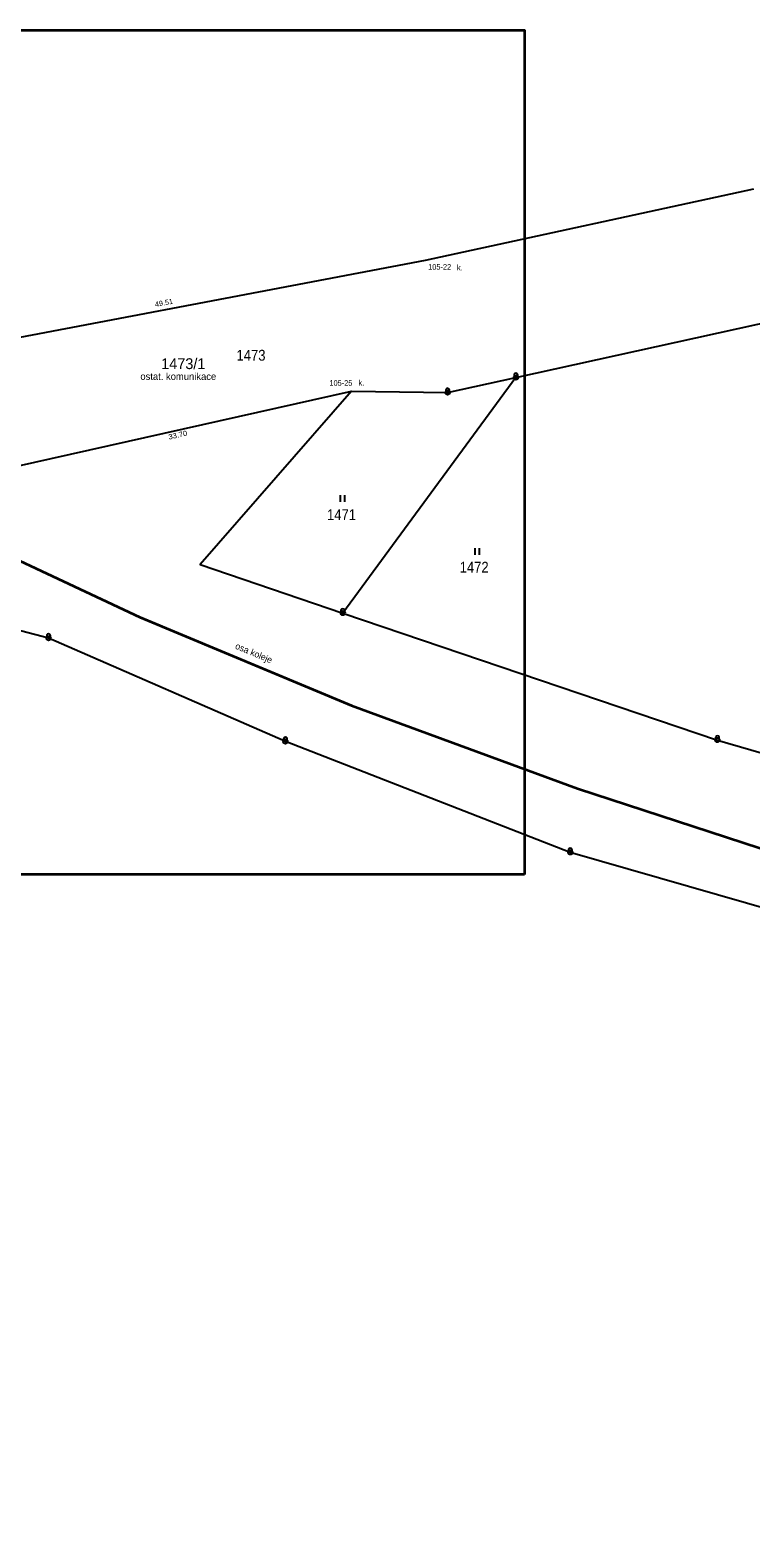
# Model space of a CAD drawing. Extents: x -871901 to -870967, y -1075952 to -1074892.
# Drawn here: x -871353.8 to -871287.2, y -1075423.5 to -1075284.3 of the extents above; entities that cross this region are included whole.
import ezdxf
from ezdxf.enums import TextEntityAlignment as Align

# ---------------------------------------------------------------- set-up
doc = ezdxf.new("R2010")
doc.units = 0
doc.header["$LTSCALE"] = 0.4
for name, color, linetype, lineweight in [('1', 7, 'Continuous', 25), ('10', 7, 'Continuous', 35), ('24', 7, 'Continuous', 25), ('25', 7, 'Continuous', 25), ('55', 7, 'Continuous', 35), ('62', 7, 'Continuous', 25)]:
    doc.layers.add(name, color=color, linetype=linetype, lineweight=lineweight)
for name, color, linetype in [('18', 7, 'Continuous'), ('54', 7, 'Continuous'), ('56', 7, 'Continuous'), ('61', 7, 'Continuous')]:
    doc.layers.add(name, color=color, linetype=linetype)

msp = doc.modelspace()

# ---------------------------------------------------------------- linework, layer by layer
at = {"layer": '1'}
for p, q in [((-871317.28, -1075305.51), (-871286.96, -1075298.91)), ((-871308.94, -1075316.35), (-871324.93, -1075338.1)), ((-871356.98, -1075324.98), (-871324.12, -1075317.6))]:
    msp.add_line(p, q, dxfattribs=at)
for points in [[(-871377.38, -1075316.93), (-871365.94, -1075314.75), (-871317.28, -1075305.51)], [(-871324.12, -1075317.6), (-871315.25, -1075317.74), (-871308.94, -1075316.35), (-871284.79, -1075311.01)], [(-871324.12, -1075317.6), (-871338.12, -1075333.63), (-871324.93, -1075338.1), (-871290.33, -1075349.84), (-871243.8, -1075363.33)], [(-871212.24, -1075392.84), (-871218.94, -1075390.82), (-871230.33, -1075381.38), (-871303.93, -1075360.22), (-871330.24, -1075349.97), (-871352.11, -1075340.43), (-871367.76, -1075336.32)]]:
    msp.add_lwpolyline(points, dxfattribs=at)
at = {"layer": '10'}
for points in [[(-871416.88, -1075301.49), (-871364.43, -1075328.75), (-871343.69, -1075338.47), (-871324.13, -1075346.64), (-871303.26, -1075354.3)], [(-871303.26, -1075354.3), (-871283.38, -1075360.82), (-871232.19, -1075375.42), (-871192.83, -1075386.61), (-871111.78, -1075409.09), (-871082.8, -1075416.75), (-871053.48, -1075423.53)]]:
    msp.add_lwpolyline(points, dxfattribs=at)
at = {"layer": '24'}
for centre, radius in [((-871308.9395, -1075316.3495), 0.2005), ((-871315.2495, -1075317.7395), 0.2005), ((-871308.9395, -1075316.3495), 0.00851), ((-871315.2495, -1075317.7395), 0.00851), ((-871324.9295, -1075338.0995), 0.2005), ((-871324.9295, -1075338.0995), 0.00851), ((-871352.1095, -1075340.4295), 0.2005), ((-871352.1095, -1075340.4295), 0.00851), ((-871330.2395, -1075349.9695), 0.2005), ((-871330.2395, -1075349.9695), 0.00851), ((-871290.3295, -1075349.8395), 0.2005), ((-871290.3295, -1075349.8395), 0.00851), ((-871303.9295, -1075360.2195), 0.2005), ((-871303.9295, -1075360.2195), 0.00851)]:
    msp.add_circle(centre, radius, dxfattribs=at)
for centre in [(-871308.9398, -1075316.1236), (-871315.2498, -1075317.5136), (-871324.9298, -1075337.8736), (-871352.1098, -1075340.2036), (-871330.2398, -1075349.7436), (-871290.3298, -1075349.6136), (-871303.9298, -1075359.9936)]:
    msp.add_arc(centre, 0.1746, 328.19485, 209.95045, dxfattribs=at)
at = {"layer": '25'}
for p, q in [((-871325.146, -1075327.825), (-871325.146, -1075327.225)), ((-871324.733, -1075327.825), (-871324.733, -1075327.225)), ((-871312.706, -1075332.725), (-871312.706, -1075332.125)), ((-871312.293, -1075332.725), (-871312.293, -1075332.125))]:
    msp.add_line(p, q, dxfattribs=at)
at = {"layer": '55'}
msp.add_lwpolyline([(-871308.16, -1075362.26), (-871420.16, -1075362.26), (-871420.16, -1075284.26), (-871308.16, -1075284.26)], close=True, dxfattribs=at)

# ---------------------------------------------------------------- texts
at = {"layer": '18', "width": 0.9}
for s, p in [('1473', (-871334.75, -1075314.79)), ('1471', (-871326.39, -1075329.52)), ('1472', (-871314.14, -1075334.37))]:
    msp.add_text(s, height=1, dxfattribs=at).set_placement(p)
at = {"layer": '54', "width": 0.95}
for s, p in [('105-22', (-871317.05, -1075306.39)), ('105-25', (-871326.17, -1075317.11))]:
    msp.add_text(s, height=0.52, dxfattribs=at).set_placement(p)
at = {"layer": '54'}
for s, rotation, width, p in [('49.51', 10.7, 1.05, (-871341.4146, -1075309.6826)), ('33.70', 12.6, 1.1, (-871340.1224, -1075321.8933))]:
    msp.add_text(s, height=0.48, rotation=rotation, dxfattribs=dict(at, width=width)).set_placement(p, align=Align.CENTER)
at = {"layer": '56'}
msp.add_text('ostat. komunikace', height=0.65, dxfattribs=at).set_placement((-871343.63, -1075316.57))
msp.add_text('osa koleje', height=0.6, rotation=337.303, dxfattribs=at).set_placement((-871333.2648, -1075342.0637), align=Align.CENTER)
at = {"layer": '61'}
for p in [(-871314.39, -1075306.45), (-871323.48, -1075317.09)]:
    msp.add_text('k.', height=0.52, dxfattribs=at).set_placement(p)
at = {"layer": '62'}
msp.add_text('1473/1', height=1, dxfattribs=at).set_placement((-871341.71, -1075315.57))

doc.saveas('drawing.dxf')
